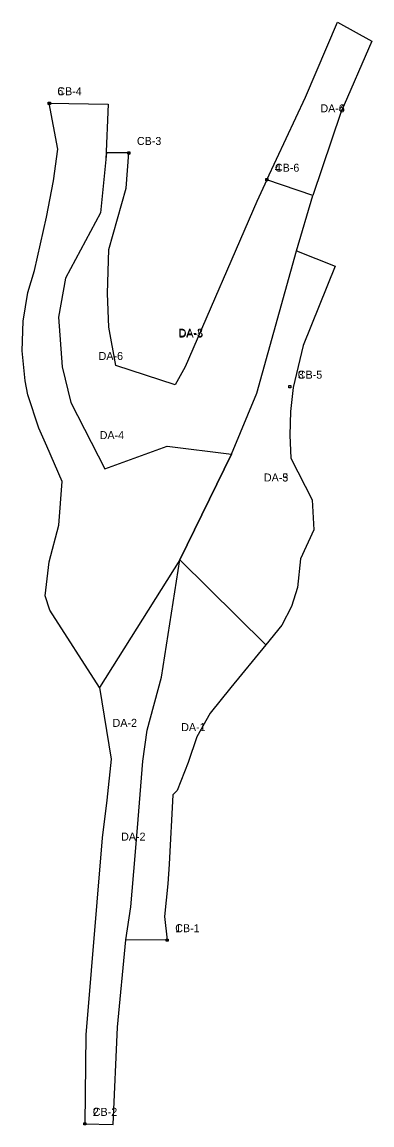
# Model space of a CAD drawing. Extents: x 1564725 to 1564969, y 636090 to 636861.
import ezdxf

# ---------------------------------------------------------------- set-up
doc = ezdxf.new("R2010")
doc.units = 0
for name, color, linetype in [('Default', 7, 'Continuous'), ('DR_P_Cells', 7, 'Continuous'), ('DT_X_Contour_Minor', 7, 'Continuous'), ('DT_X_Void', 7, 'Continuous')]:
    doc.layers.add(name, color=color, linetype=linetype)

# ---------------------------------------------------------------- blocks, each defined once
blk = doc.blocks.new('catchbasin')
at = {"layer": 'Default'}
for p, q in [((-0.762, 0.762), (0.762, 0.762)), ((-0.762, -0.762), (-0.762, 0.762)), ((0.762, 0.762), (0.762, -0.762)), ((0.762, -0.762), (-0.762, -0.762))]:
    blk.add_line(p, q, dxfattribs=at)

msp = doc.modelspace()

# ---------------------------------------------------------------- linework, layer by layer
at = {"layer": 'DT_X_Void'}
for points in [[(1564945.33, 636861.4), (1564969.39, 636848.08), (1564947.64, 636798.23), (1564928.1, 636740.14), (1564895.96, 636751.1), (1564922.84, 636808.89)], [(1564743.82, 636804.58), (1564785, 636803.93), (1564783.27, 636765.15), (1564779.5, 636727.99), (1564755.11, 636682.2), (1564750.33, 636654.89), (1564752.74, 636620.29), (1564758.97, 636595.14), (1564782.6, 636548.81), (1564826.21, 636564.69), (1564871.13, 636559.13), (1564834.99, 636485.1), (1564779, 636395.94), (1564744.15, 636449.87), (1564740.89, 636459.89), (1564743.8, 636483.82), (1564750.39, 636509.46), (1564752.87, 636539.88), (1564742.15, 636564.59), (1564736.43, 636577.24), (1564728.87, 636600.69), (1564726.88, 636610.48), (1564724.77, 636631.48), (1564725.47, 636652.08), (1564728.86, 636672.29), (1564733.39, 636687.67), (1564741.87, 636724.86), (1564746.72, 636750.3), (1564749.84, 636772.4)], [(1564826.21, 636564.69), (1564871.13, 636559.13), (1564889.03, 636601.7), (1564916.58, 636701.31), (1564928.1, 636740.14), (1564895.96, 636751.1), (1564888.9, 636735.86), (1564838.79, 636620.25), (1564831.85, 636607.54), (1564790.41, 636621.22), (1564785.41, 636647.91), (1564784.43, 636671.51), (1564785.55, 636702.28), (1564797.58, 636745.13), (1564799.33, 636769.85), (1564783.74, 636769.84), (1564779.5, 636727.99), (1564755.11, 636682.2), (1564750.33, 636654.89), (1564752.74, 636620.29), (1564758.97, 636595.14), (1564782.6, 636548.81)], [(1564916.58, 636701.31), (1564943.68, 636690.67), (1564921.35, 636635.08), (1564914.4, 636605.62), (1564912.45, 636588.94), (1564911.93, 636572.27), (1564912.76, 636556.39), (1564927.58, 636527.03), (1564928.86, 636506.06), (1564919.48, 636485.87), (1564917.39, 636465.84), (1564913.19, 636452.58), (1564906.43, 636439.42), (1564895.19, 636425.76), (1564834.99, 636485.1), (1564871.13, 636559.13), (1564889.03, 636601.7)], [(1564769.27, 636152.74), (1564768.64, 636090.55), (1564788.54, 636090.01), (1564791.54, 636158.21), (1564797.34, 636219.39), (1564800.71, 636242.44), (1564803.8, 636278.18), (1564806, 636303.58), (1564809.32, 636344.27), (1564812.19, 636365.99), (1564822.24, 636403.14), (1564834.99, 636485.1), (1564779, 636395.94), (1564787.04, 636345.63), (1564784.12, 636316.97), (1564780.79, 636290.62)], [(1564826.26, 636219.06), (1564797.34, 636219.39), (1564800.71, 636242.44), (1564803.8, 636278.18), (1564806, 636303.58), (1564809.32, 636344.27), (1564812.19, 636365.99), (1564822.24, 636403.14), (1564834.99, 636485.1), (1564895.13, 636425.75), (1564870.83, 636395.73), (1564856.3, 636377.79), (1564846.97, 636361.31), (1564841, 636343.26), (1564833.31, 636323.72), (1564830.25, 636320.72), (1564827.69, 636272.15), (1564826.79, 636258.52), (1564824.43, 636235.55)]]:
    msp.add_lwpolyline(points, close=True, dxfattribs=at)

# ---------------------------------------------------------------- block references
at = {"layer": 'DT_X_Contour_Minor'}
for p in [(1564743.82, 636804.58), (1564743.82, 636804.58), (1564799.47, 636769.81), (1564895.96, 636751.1), (1564895.96, 636751.1), (1564911.98, 636606.3), (1564911.98, 636606.3), (1564826.26, 636219.06), (1564826.26, 636219.06), (1564768.64, 636090.55)]:
    msp.add_blockref('catchbasin', p, dxfattribs=at)

# ---------------------------------------------------------------- texts
at = {"layer": 'DR_P_Cells'}
for s, p in [('CB-4', (1564749.42, 636810.18)), ('6', (1564749.42, 636810.18)), ('DA-6', (1564933.36, 636798.25)), ('DA-4', (1564933.36, 636798.25)), ('CB-3', (1564805.07, 636775.41)), ('4', (1564901.56, 636756.7)), ('CB-6', (1564901.56, 636756.7)), ('DA-3', (1564834.1, 636641.28)), ('DA-5', (1564834.3, 636640.69)), ('DA-6', (1564778.29, 636624.96)), ('3', (1564917.58, 636611.9)), ('CB-5', (1564917.58, 636611.9)), ('DA-4', (1564779.04, 636569.6)), ('DA-3', (1564893.84, 636539.97)), ('DA-5', (1564893.84, 636539.97)), ('DA-2', (1564788.07, 636368.31)), ('DA-1', (1564836.02, 636365.32)), ('DA-1', (1564836.02, 636365.32)), ('DA-2', (1564794.01, 636288.7)), ('CB-1', (1564831.86, 636224.66)), ('1', (1564831.86, 636224.66)), ('CB-2', (1564774.24, 636096.15)), ('2', (1564774.24, 636096.15))]:
    msp.add_text(s, height=5.6, dxfattribs=at).set_placement(p)

doc.saveas('drawing.dxf')
